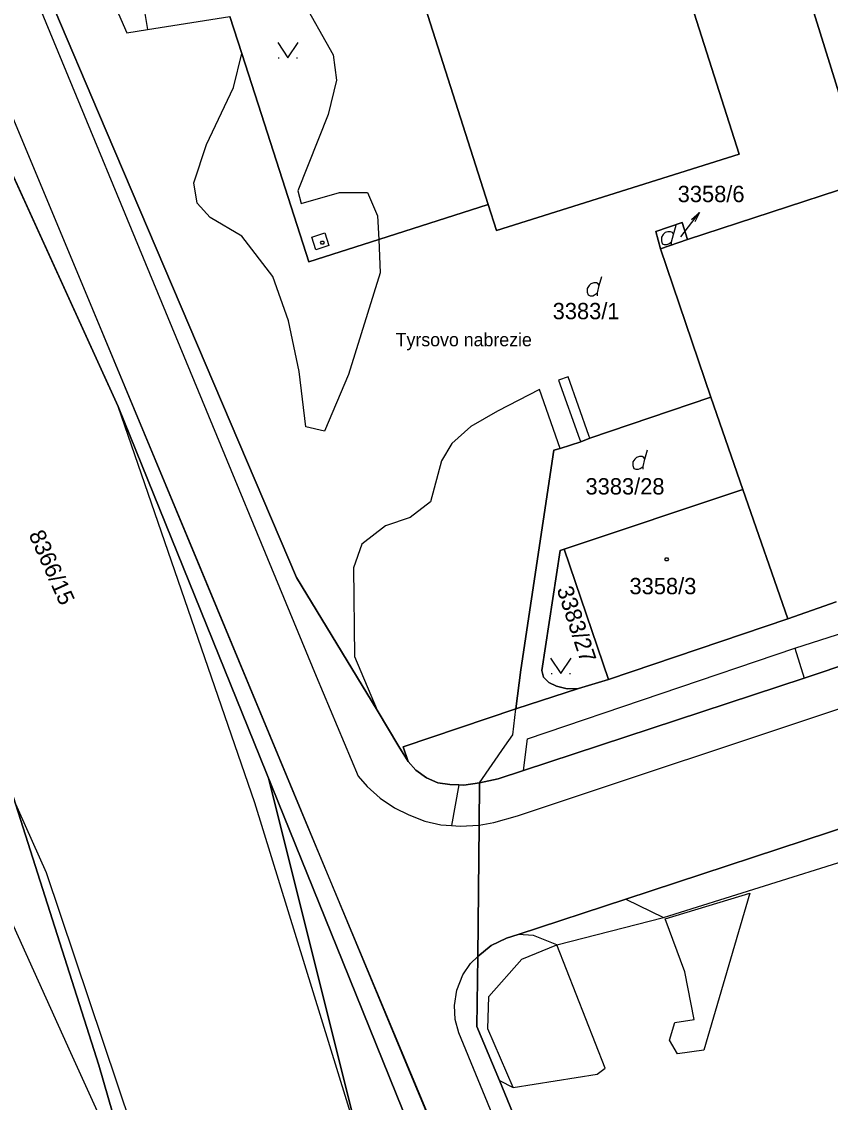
# Model space of a CAD drawing. Extents: x -263587 to -261993, y -1238795 to -1236748.
# Drawn here: x -262850.7 to -262771.6, y -1238673.4 to -1238567.5 of the extents above; entities that cross this region are included whole.
import ezdxf

# ---------------------------------------------------------------- set-up
doc = ezdxf.new("R2010")
doc.units = 0
for name, color, linetype in [('Vrstva 1', 7, 'Continuous'), ('Vrstva 2', 7, 'Continuous'), ('Vrstva 3', 7, 'Continuous')]:
    doc.layers.add(name, color=color, linetype=linetype)

msp = doc.modelspace()

# ---------------------------------------------------------------- linework, layer by layer
at = {"layer": 'Vrstva 1'}
for p, q in [((-262867.87, -1238520.38), (-262821.9, -1238631.6)), ((-262840.03, -1238558.87), (-262838.41, -1238568.24)), ((-262786.53, -1238561.5), (-262780.51, -1238580.47)), ((-262780.51, -1238580.47), (-262786.53, -1238561.5)), ((-262769.95, -1238576.95), (-262774.47, -1238562.46)), ((-262774.47, -1238562.46), (-262769.95, -1238576.95)), ((-262823.64, -1238564.66), (-262820.23, -1238570.74)), ((-262841.93, -1238565.11), (-262840.43, -1238568.57)), ((-262811.45, -1238565.3), (-262805.06, -1238585.39)), ((-262805.06, -1238585.39), (-262811.45, -1238565.3)), ((-262847.5, -1238566.36), (-262843.22, -1238576.41)), ((-262843.22, -1238576.41), (-262847.5, -1238566.36)), ((-262838.41, -1238568.24), (-262830.35, -1238566.96)), ((-262829.18, -1238570.6), (-262830.35, -1238566.96)), ((-262830.35, -1238566.96), (-262829.18, -1238570.6)), ((-262840.43, -1238568.57), (-262838.41, -1238568.24)), ((-262830.01, -1238573.94), (-262829.18, -1238570.6)), ((-262827.26, -1238576.59), (-262829.18, -1238570.6)), ((-262829.18, -1238570.6), (-262827.26, -1238576.59)), ((-262825.62, -1238571.01), (-262825.52, -1238571.01)), ((-262823.82, -1238571.01), (-262823.72, -1238571.01)), ((-262820.23, -1238570.74), (-262819.93, -1238573.22)), ((-262853.67, -1238572), (-262833.9, -1238619.38)), ((-262819.93, -1238573.22), (-262820.72, -1238576.56)), ((-262855.68, -1238573.6), (-262841.29, -1238605.19)), ((-262841.29, -1238605.19), (-262855.68, -1238573.6)), ((-262832.64, -1238579.5), (-262830.01, -1238573.94)), ((-262843.22, -1238576.41), (-262823.83, -1238621.93)), ((-262823.83, -1238621.93), (-262843.22, -1238576.41)), ((-262820.72, -1238576.56), (-262823.69, -1238584.06)), ((-262822.62, -1238591), (-262827.26, -1238576.59)), ((-262827.26, -1238576.59), (-262822.62, -1238591)), ((-262833.89, -1238583.27), (-262832.64, -1238579.5)), ((-262848.3, -1238650.86), (-262879.8, -1238580.61)), ((-262780.51, -1238580.47), (-262804.25, -1238587.93)), ((-262804.25, -1238587.93), (-262780.51, -1238580.47)), ((-262833.57, -1238585.26), (-262833.89, -1238583.27)), ((-262768.04, -1238583.09), (-262785.54, -1238588.81)), ((-262785.54, -1238588.81), (-262768.04, -1238583.09)), ((-262823.69, -1238584.06), (-262823.37, -1238585.3)), ((-262823.37, -1238585.3), (-262819.61, -1238584.2)), ((-262819.61, -1238584.2), (-262816.87, -1238584.23)), ((-262816.87, -1238584.23), (-262815.89, -1238586.51)), ((-262832.27, -1238586.67), (-262833.57, -1238585.26)), ((-262805.06, -1238585.39), (-262815.78, -1238588.82)), ((-262815.78, -1238588.82), (-262805.06, -1238585.39)), ((-262804.25, -1238587.93), (-262805.06, -1238585.39)), ((-262805.06, -1238585.39), (-262804.25, -1238587.93)), ((-262829.2, -1238588.48), (-262832.27, -1238586.67)), ((-262815.89, -1238586.51), (-262815.78, -1238588.82)), ((-262785.155, -1238586.855), (-262784.385, -1238586.187)), ((-262822.33, -1238588.58), (-262821.06, -1238588.18)), ((-262821.06, -1238588.18), (-262820.67, -1238589.42)), ((-262786.09, -1238587.16), (-262788.67, -1238588.04)), ((-262788.67, -1238588.04), (-262786.09, -1238587.16)), ((-262788.67, -1238588.04), (-262788.2, -1238589.74)), ((-262788.2, -1238589.74), (-262788.67, -1238588.04)), ((-262786.94, -1238588.33), (-262786.67, -1238587.43)), ((-262785.54, -1238588.81), (-262786.09, -1238587.16)), ((-262786.09, -1238587.16), (-262785.54, -1238588.81)), ((-262826.15, -1238592.46), (-262829.2, -1238588.48)), ((-262815.78, -1238588.82), (-262822.62, -1238591)), ((-262822.62, -1238591), (-262815.78, -1238588.82)), ((-262821.94, -1238589.82), (-262822.33, -1238588.58)), ((-262815.78, -1238588.82), (-262815.63, -1238592.07)), ((-262785.54, -1238588.81), (-262788.2, -1238589.74)), ((-262788.2, -1238589.74), (-262785.54, -1238588.81)), ((-262820.67, -1238589.42), (-262821.94, -1238589.82)), ((-262788.2, -1238589.74), (-262783.26, -1238604.28)), ((-262783.26, -1238604.28), (-262788.2, -1238589.74)), ((-262815.63, -1238592.07), (-262818.73, -1238602.04)), ((-262794.2, -1238593.34), (-262793.93, -1238592.44)), ((-262824.63, -1238596.78), (-262826.15, -1238592.46)), ((-262823.57, -1238601.76), (-262824.63, -1238596.78)), ((-262822.91, -1238607.18), (-262823.57, -1238601.76)), ((-262818.73, -1238602.04), (-262821.09, -1238607.61)), ((-262797.24, -1238602.28), (-262798.17, -1238602.6)), ((-262798.17, -1238602.6), (-262796.14, -1238608.35)), ((-262795.2, -1238608.02), (-262797.24, -1238602.28)), ((-262800.05, -1238603.52), (-262804.14, -1238605.64)), ((-262798.03, -1238609.31), (-262800.05, -1238603.52)), ((-262795.11, -1238608.29), (-262783.26, -1238604.28)), ((-262783.26, -1238604.28), (-262795.11, -1238608.29)), ((-262783.26, -1238604.28), (-262780.15, -1238613.32)), ((-262780.15, -1238613.32), (-262783.26, -1238604.28)), ((-262841.29, -1238605.19), (-262819.3, -1238659.58)), ((-262819.3, -1238659.58), (-262841.29, -1238605.19)), ((-262827.91, -1238643.99), (-262841.29, -1238605.19)), ((-262804.14, -1238605.64), (-262806.75, -1238607.15)), ((-262821.09, -1238607.61), (-262822.91, -1238607.18)), ((-262806.75, -1238607.15), (-262808.64, -1238608.8)), ((-262796.01, -1238608.64), (-262795.11, -1238608.29)), ((-262795.11, -1238608.29), (-262796.01, -1238608.64)), ((-262795.11, -1238608.29), (-262795.2, -1238608.02)), ((-262808.64, -1238608.8), (-262809.63, -1238610.5)), ((-262798.63, -1238609.46), (-262798.03, -1238609.31)), ((-262798.03, -1238609.31), (-262798.63, -1238609.46)), ((-262798.03, -1238609.31), (-262796.01, -1238608.64)), ((-262796.01, -1238608.64), (-262798.03, -1238609.31)), ((-262796.14, -1238608.35), (-262796.01, -1238608.64)), ((-262801.88, -1238630.97), (-262798.63, -1238609.46)), ((-262798.63, -1238609.46), (-262801.88, -1238630.97)), ((-262789.73, -1238610.34), (-262789.46, -1238609.44)), ((-262809.63, -1238610.5), (-262810.72, -1238614.52)), ((-262797.62, -1238619.16), (-262780.15, -1238613.32)), ((-262780.15, -1238613.32), (-262797.62, -1238619.16)), ((-262780.15, -1238613.32), (-262775.73, -1238625.98)), ((-262775.73, -1238625.98), (-262780.15, -1238613.32)), ((-262810.72, -1238614.52), (-262812.69, -1238616.05)), ((-262812.69, -1238616.05), (-262815.12, -1238616.87)), ((-262815.12, -1238616.87), (-262817.43, -1238618.67)), ((-262817.43, -1238618.67), (-262818.25, -1238620.97)), ((-262833.9, -1238619.38), (-262812.83, -1238670.19)), ((-262798.02, -1238619.29), (-262799.81, -1238631.03)), ((-262799.81, -1238631.03), (-262798.02, -1238619.29)), ((-262797.62, -1238619.16), (-262798.02, -1238619.29)), ((-262798.02, -1238619.29), (-262797.62, -1238619.16)), ((-262793.29, -1238631.93), (-262797.62, -1238619.16)), ((-262797.62, -1238619.16), (-262793.29, -1238631.93)), ((-262818.25, -1238620.97), (-262818.15, -1238629.68)), ((-262823.83, -1238621.93), (-262815.95, -1238634.93)), ((-262815.95, -1238634.93), (-262823.83, -1238621.93)), ((-262771.01, -1238624.31), (-262775.73, -1238625.98)), ((-262775.73, -1238625.98), (-262771.01, -1238624.31)), ((-262775.73, -1238625.98), (-262793.29, -1238631.93)), ((-262793.29, -1238631.93), (-262775.73, -1238625.98)), ((-262775.04, -1238628.86), (-262770.06, -1238627.24)), ((-262801.22, -1238637.75), (-262775.04, -1238628.86)), ((-262775.04, -1238628.86), (-262774.15, -1238631.78)), ((-262818.15, -1238629.68), (-262815.95, -1238634.93)), ((-262774.15, -1238631.78), (-262769.15, -1238630.12)), ((-262769.15, -1238630.12), (-262774.15, -1238631.78)), ((-262821.9, -1238631.6), (-262817.8, -1238641.4)), ((-262802.35, -1238634.79), (-262801.88, -1238630.97)), ((-262801.88, -1238630.97), (-262802.35, -1238634.79)), ((-262799.81, -1238631.03), (-262799.64, -1238631.71)), ((-262799.64, -1238631.71), (-262799.81, -1238631.03)), ((-262798.91, -1238631.34), (-262798.81, -1238631.34)), ((-262797.11, -1238631.34), (-262797.01, -1238631.34)), ((-262802.2, -1238645.27), (-262762.82, -1238632.15)), ((-262801.62, -1238640.83), (-262774.15, -1238631.78)), ((-262774.15, -1238631.78), (-262801.62, -1238640.83)), ((-262799.64, -1238631.71), (-262799.14, -1238632.23)), ((-262799.14, -1238632.23), (-262799.64, -1238631.71)), ((-262799.14, -1238632.23), (-262798.37, -1238632.59)), ((-262798.37, -1238632.59), (-262799.14, -1238632.23)), ((-262798.37, -1238632.59), (-262797.34, -1238632.83)), ((-262797.34, -1238632.83), (-262798.37, -1238632.59)), ((-262793.29, -1238631.93), (-262796.24, -1238632.8)), ((-262796.24, -1238632.8), (-262793.29, -1238631.93)), ((-262796.24, -1238632.8), (-262802.35, -1238634.79)), ((-262802.35, -1238634.79), (-262796.24, -1238632.8)), ((-262797.34, -1238632.83), (-262796.24, -1238632.8)), ((-262796.24, -1238632.8), (-262797.34, -1238632.83)), ((-262802.35, -1238634.79), (-262813.39, -1238638.51)), ((-262813.39, -1238638.51), (-262802.35, -1238634.79)), ((-262802.67, -1238637.34), (-262802.35, -1238634.79)), ((-262815.95, -1238634.93), (-262813.8, -1238638.49)), ((-262813.8, -1238638.49), (-262815.95, -1238634.93)), ((-262803.44, -1238638.47), (-262802.67, -1238637.34)), ((-262801.62, -1238640.83), (-262801.22, -1238637.75)), ((-262813.8, -1238638.49), (-262812.89, -1238639.95)), ((-262812.89, -1238639.95), (-262813.8, -1238638.49)), ((-262813.39, -1238638.51), (-262812.89, -1238639.95)), ((-262812.89, -1238639.95), (-262813.39, -1238638.51)), ((-262805.93, -1238642.04), (-262803.44, -1238638.47)), ((-262812.89, -1238639.95), (-262812.14, -1238640.8)), ((-262812.14, -1238640.8), (-262812.89, -1238639.95)), ((-262812.14, -1238640.8), (-262811.11, -1238641.54)), ((-262811.11, -1238641.54), (-262812.14, -1238640.8)), ((-262804.08, -1238641.65), (-262801.62, -1238640.83)), ((-262801.62, -1238640.83), (-262804.08, -1238641.65)), ((-262817.8, -1238641.4), (-262816.91, -1238642.4)), ((-262811.11, -1238641.54), (-262810, -1238642.05)), ((-262810, -1238642.05), (-262811.11, -1238641.54)), ((-262810, -1238642.05), (-262808.83, -1238642.2)), ((-262808.83, -1238642.2), (-262810, -1238642.05)), ((-262808.83, -1238642.2), (-262807.94, -1238642.25)), ((-262807.94, -1238642.25), (-262808.83, -1238642.2)), ((-262807.45, -1238642.27), (-262805.93, -1238642.04)), ((-262805.93, -1238642.04), (-262807.45, -1238642.27)), ((-262805.93, -1238642.04), (-262805.94, -1238646.19)), ((-262805.94, -1238646.19), (-262805.93, -1238642.04)), ((-262805.93, -1238642.04), (-262804.08, -1238641.65)), ((-262804.08, -1238641.65), (-262805.93, -1238642.04)), ((-262816.91, -1238642.4), (-262815.65, -1238643.54)), ((-262807.94, -1238642.25), (-262808.66, -1238646.24)), ((-262807.94, -1238642.25), (-262807.45, -1238642.27)), ((-262807.45, -1238642.27), (-262807.94, -1238642.25)), ((-262817.69, -1238677.08), (-262827.91, -1238643.99)), ((-262815.65, -1238643.54), (-262814.24, -1238644.5)), ((-262791.59, -1238653.43), (-262762.99, -1238644.02)), ((-262762.99, -1238644.02), (-262791.59, -1238653.43)), ((-262814.24, -1238644.5), (-262812.84, -1238645.19)), ((-262812.84, -1238645.19), (-262811.27, -1238645.8)), ((-262804.51, -1238645.93), (-262802.2, -1238645.27)), ((-262811.27, -1238645.8), (-262809.7, -1238646.17)), ((-262809.7, -1238646.17), (-262808.66, -1238646.24)), ((-262808.66, -1238646.24), (-262807.8, -1238646.3)), ((-262807.8, -1238646.3), (-262805.94, -1238646.19)), ((-262805.94, -1238646.19), (-262806.09, -1238659.07)), ((-262806.09, -1238659.07), (-262805.94, -1238646.19)), ((-262805.94, -1238646.19), (-262804.51, -1238645.93)), ((-262787.91, -1238655.23), (-262757.18, -1238645.61)), ((-262828.77, -1238709.14), (-262848.3, -1238650.86)), ((-262802.12, -1238656.89), (-262791.59, -1238653.43)), ((-262791.59, -1238653.43), (-262802.12, -1238656.89)), ((-262791.59, -1238653.43), (-262787.91, -1238655.23)), ((-262787.73, -1238655.36), (-262779.47, -1238652.87)), ((-262779.47, -1238652.87), (-262783.95, -1238668.25)), ((-262798.34, -1238657.9), (-262787.91, -1238655.23)), ((-262785.82, -1238660.56), (-262787.73, -1238655.36)), ((-262803.27, -1238657.27), (-262802.12, -1238656.89)), ((-262802.12, -1238656.89), (-262803.27, -1238657.27)), ((-262800.62, -1238656.99), (-262802.12, -1238656.89)), ((-262798.34, -1238657.9), (-262800.62, -1238656.99)), ((-262806.09, -1238659.07), (-262804.77, -1238657.97)), ((-262804.77, -1238657.97), (-262806.09, -1238659.07)), ((-262804.77, -1238657.97), (-262803.27, -1238657.27)), ((-262803.27, -1238657.27), (-262804.77, -1238657.97)), ((-262801.76, -1238659.33), (-262798.34, -1238657.9)), ((-262793.63, -1238670.01), (-262798.34, -1238657.9)), ((-262806.8, -1238659.76), (-262806.09, -1238659.07)), ((-262806.17, -1238665.92), (-262806.09, -1238659.07)), ((-262806.09, -1238659.07), (-262806.17, -1238665.92)), ((-262819.3, -1238659.58), (-262797.31, -1238714.08)), ((-262797.31, -1238714.08), (-262819.3, -1238659.58)), ((-262807.55, -1238660.86), (-262806.8, -1238659.76)), ((-262805.02, -1238662.98), (-262801.76, -1238659.33)), ((-262808.13, -1238662.37), (-262807.55, -1238660.86)), ((-262784.91, -1238665.23), (-262785.82, -1238660.56)), ((-262808.36, -1238663.85), (-262808.13, -1238662.37)), ((-262805.1, -1238666.16), (-262805.02, -1238662.98)), ((-262808.3, -1238665.22), (-262808.36, -1238663.85)), ((-262807.95, -1238666.54), (-262808.3, -1238665.22)), ((-262786.8, -1238665.54), (-262784.91, -1238665.23)), ((-262779.17, -1238736.31), (-262807.95, -1238666.54)), ((-262803.97, -1238671.2), (-262806.17, -1238665.92)), ((-262806.17, -1238665.92), (-262803.97, -1238671.2)), ((-262802.61, -1238671.89), (-262805.1, -1238666.16)), ((-262787.33, -1238667.26), (-262786.8, -1238665.54)), ((-262786.52, -1238668.6), (-262787.33, -1238667.26)), ((-262783.95, -1238668.25), (-262786.52, -1238668.6)), ((-262812.83, -1238670.19), (-262795.34, -1238712.3)), ((-262802.61, -1238671.89), (-262794.41, -1238670.59)), ((-262794.41, -1238670.59), (-262793.63, -1238670.01)), ((-262801.04, -1238678.25), (-262803.97, -1238671.2)), ((-262803.97, -1238671.2), (-262801.04, -1238678.25)), ((-262803.97, -1238671.2), (-262802.61, -1238671.89))]:
    msp.add_line(p, q, dxfattribs=at)
for points in [[(-262825.67, -1238569.51), (-262824.67, -1238571.01), (-262823.67, -1238569.51)], [(-262786.22, -1238588.56), (-262784.385, -1238586.187), (-262784.838, -1238587.1)], [(-262787.12, -1238589.32), (-262787.12, -1238589.05), (-262786.94, -1238588.33), (-262787.03, -1238588.15), (-262787.21, -1238588.06), (-262787.48, -1238588.06), (-262787.75, -1238588.15), (-262787.93, -1238588.33), (-262788.11, -1238588.6), (-262788.11, -1238588.96), (-262788.02, -1238589.23), (-262787.84, -1238589.32), (-262787.57, -1238589.32), (-262787.39, -1238589.23), (-262787.12, -1238589.05)], [(-262794.38, -1238594.33), (-262794.38, -1238594.06), (-262794.2, -1238593.34), (-262794.29, -1238593.16), (-262794.47, -1238593.07), (-262794.74, -1238593.07), (-262795.01, -1238593.16), (-262795.19, -1238593.34), (-262795.37, -1238593.61), (-262795.37, -1238593.97), (-262795.28, -1238594.24), (-262795.1, -1238594.33), (-262794.83, -1238594.33), (-262794.65, -1238594.24), (-262794.38, -1238594.06)], [(-262789.91, -1238611.33), (-262789.91, -1238611.06), (-262789.73, -1238610.34), (-262789.82, -1238610.16), (-262790, -1238610.07), (-262790.27, -1238610.07), (-262790.54, -1238610.16), (-262790.72, -1238610.34), (-262790.9, -1238610.61), (-262790.9, -1238610.97), (-262790.81, -1238611.24), (-262790.63, -1238611.33), (-262790.36, -1238611.33), (-262790.18, -1238611.24), (-262789.91, -1238611.06)], [(-262798.96, -1238629.84), (-262797.96, -1238631.34), (-262796.96, -1238629.84)]]:
    msp.add_lwpolyline(points, dxfattribs=at)
for points in [[(-262821.22, -1238588.97), (-262821.13, -1238589.12), (-262821.22, -1238589.27), (-262821.4, -1238589.27), (-262821.49, -1238589.12), (-262821.4, -1238588.97)], [(-262787.51, -1238620.01), (-262787.42, -1238620.16), (-262787.51, -1238620.31), (-262787.69, -1238620.31), (-262787.78, -1238620.16), (-262787.69, -1238620.01)]]:
    msp.add_lwpolyline(points, close=True, dxfattribs=at)
at = {"layer": 'Vrstva 2'}
msp.add_lwpolyline([(-262888.76, -1238565.07), (-262881.2, -1238585.49), (-262874.64, -1238603.32), (-262857.39, -1238650.09), (-262854.72, -1238649.06), (-262845.959, -1238668.452), (-262837.314, -1238687.515), (-262834.801, -1238686.521), (-262828.426, -1238701.842), (-262822.233, -1238701.015), (-262822.159, -1238701.403), (-262807.207, -1238697.538), (-262805.6, -1238694.49), (-262805.937, -1238690.489), (-262804.47, -1238690.03), (-262823.365, -1238644.785), (-262843.785, -1238595.69), (-262853.67, -1238572), (-262858.82, -1238561.234)], dxfattribs=at)
at = {"layer": 'Vrstva 3'}
for points in [[(-262873.07, -1238591.06), (-262856.84, -1238626.9), (-262843.17, -1238669.69), (-262829.75, -1238716.29), (-262826.989, -1238732.855), (-262832.23, -1238728.76), (-262834.78, -1238727.48), (-262837.39, -1238720.58), (-262844.59, -1238701.65), (-262854.611, -1238674.81), (-262854.62, -1238674.77), (-262855.09, -1238672.67), (-262860.52, -1238650.59), (-262863.21, -1238637.78), (-262875.49, -1238605.34), (-262879.11, -1238608.86), (-262889.51, -1238582.21), (-262897.469, -1238561.677), (-262892.81, -1238551.53)], [(-262797.31, -1238714.08), (-262790.67, -1238730.48), (-262804.77, -1238734.99), (-262806.13, -1238735.395), (-262808.03, -1238717.21), (-262810.05, -1238706.04), (-262810.57, -1238704.16), (-262810.76, -1238703.46), (-262817.69, -1238677.08), (-262826.578, -1238641.58), (-262819.3, -1238659.58)]]:
    msp.add_lwpolyline(points, close=True, dxfattribs=at)
msp.add_lwpolyline([(-262855.68, -1238573.6), (-262841.29, -1238605.19), (-262826.578, -1238641.58), (-262817.69, -1238677.08), (-262810.76, -1238703.46), (-262828.56, -1238707.59), (-262828.77, -1238709.14), (-262824.73, -1238719.13), (-262822.57, -1238722.55), (-262819.71, -1238720.81), (-262810.57, -1238704.16), (-262810.05, -1238706.04), (-262808.03, -1238717.21), (-262806.13, -1238735.395), (-262813.36, -1238737.55), (-262816.76, -1238738.13), (-262820.76, -1238737.67), (-262822.4, -1238736.44), (-262826.989, -1238732.855), (-262829.75, -1238716.29), (-262843.17, -1238669.69), (-262856.84, -1238626.9)], dxfattribs=at)

# ---------------------------------------------------------------- texts
at = {"layer": 'Vrstva 1'}
for s, height, p in [('3358/6', 1.6, (-262786.517, -1238585.16)), ('3383/1', 1.6, (-262798.754, -1238596.63)), ('Tyrsovo nabrezie', 1.3, (-262814.124, -1238599.28)), ('3383/28', 1.6, (-262795.541, -1238613.8)), ('3358/3', 1.6, (-262791.233, -1238623.57))]:
    msp.add_text(s, height=height, dxfattribs=at).set_placement(p)
for s, rotation, p in [('8366/15', 294.04194, (-262850.081, -1238617.724)), ('3383/27', 288.14048, (-262798.375, -1238623.067))]:
    msp.add_text(s, height=1.6, rotation=rotation, dxfattribs=at).set_placement(p)

doc.saveas('drawing.dxf')
